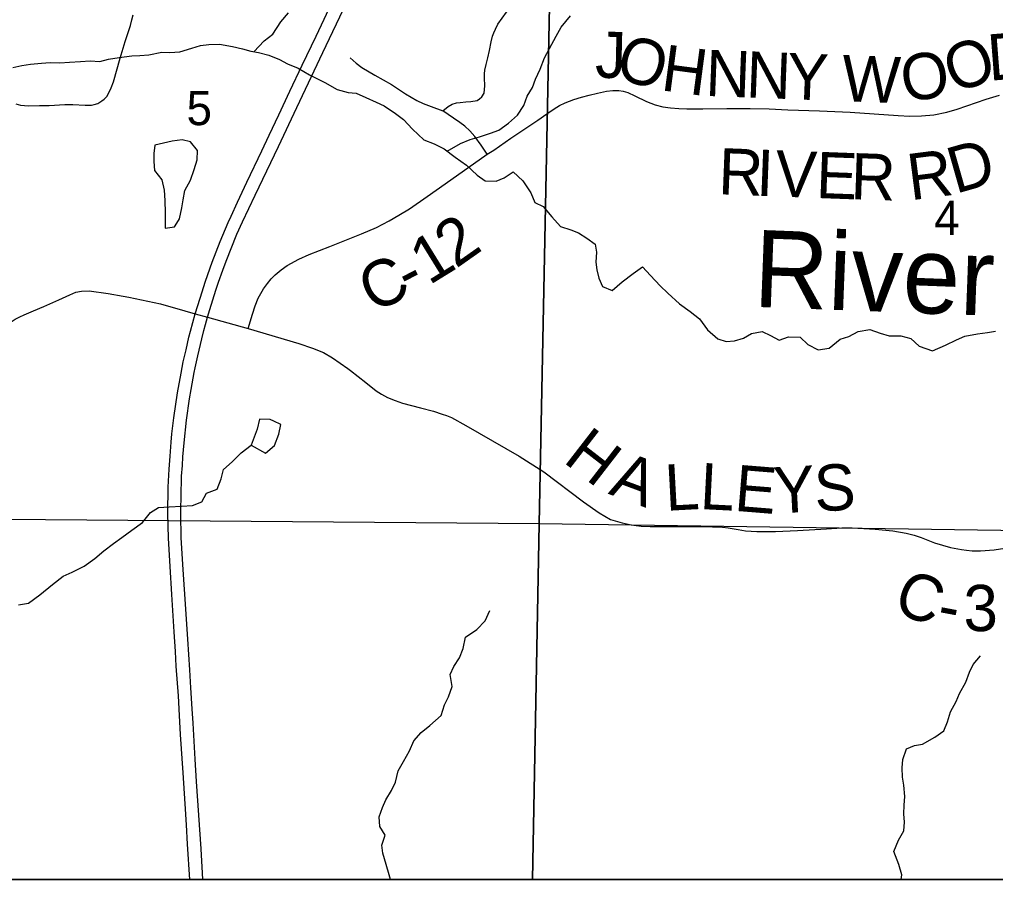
# Model space of a CAD drawing. Extents: x 0 to 34, y 0 to 22.
# Drawn here: x 6.166 to 7.364, y 14.573 to 15.63 of the extents above; entities that cross this region are included whole.
import ezdxf

# ---------------------------------------------------------------- set-up
doc = ezdxf.new("R2010")
doc.units = 0
for name, color, linetype in [('GM_X_Corporation', 7, 'Continuous'), ('GM_X_County_Road', 7, 'Continuous'), ('GM_X_County_Road_Text', 7, 'Continuous'), ('GM_X_Interstate_Route', 7, 'Continuous'), ('GM_X_Minor_Lake', 7, 'Continuous'), ('GM_X_Minor_River', 7, 'Continuous'), ('GM_X_Minor_River_Text', 7, 'Continuous'), ('GM_X_Section_Text', 7, 'Continuous'), ('GM_X_Township_Road', 7, 'Continuous'), ('SH_Text', 7, 'Continuous')]:
    doc.layers.add(name, color=color, linetype=linetype)

msp = doc.modelspace()

# ---------------------------------------------------------------- linework, layer by layer
at = {"layer": 'GM_X_Corporation'}
for points in [[(1.6311, 14.5734), (8.4311, 14.5734), (8.4311, 20.028)], [(3.7221, 14.5734), (8.4311, 14.5734), (8.4311, 16.0029), (7.8077, 16.0135), (7.8043, 16.0135), (6.9736, 16.0344), (6.9699, 16.0345), (6.7034, 16.04), (6.6909, 16.0403), (6.6873, 16.0404), (6.4721, 16.0449), (6.4668, 16.045), (5.0373, 16.0816)]]:
    msp.add_lwpolyline(points, dxfattribs=at)
for points in [[(5.82, 16.0635), (6.7585, 16.0372), (6.8244, 16.0368), (6.804, 15.0104), (5.7937, 15.0184)], [(6.8244, 16.0368), (7.8046, 16.0144), (7.7958, 14.9961), (6.804, 15.0104)], [(5.7869, 14.5734), (6.7958, 14.5734), (6.804, 15.0104), (5.7937, 15.0184)], [(6.7958, 14.5734), (7.7879, 14.5734), (7.7958, 14.9961), (6.804, 15.0104)]]:
    msp.add_lwpolyline(points, close=True, dxfattribs=at)
at = {"layer": 'GM_X_County_Road'}
for points in [[(6.296, 15.6029), (6.3022, 15.6226), (6.3042, 15.6295), (6.3057, 15.6357)], [(6.1617, 15.5261), (6.1673, 15.5246), (6.1721, 15.5241), (6.1773, 15.5239), (6.1905, 15.5241), (6.2027, 15.5241), (6.2217, 15.5253), (6.2317, 15.5253), (6.2469, 15.5246), (6.2543, 15.5247), (6.2577, 15.5252), (6.2621, 15.5267), (6.2673, 15.5297), (6.2701, 15.5319), (6.2732, 15.5353), (6.2763, 15.5404), (6.2787, 15.5459), (6.2814, 15.5532), (6.2898, 15.5824), (6.2933, 15.5944), (6.296, 15.6029)], [(6.8654, 15.5369), (6.8758, 15.5393), (6.8866, 15.5416), (6.8946, 15.5427), (6.902, 15.5427), (6.9071, 15.5419), (6.913, 15.5402), (6.9215, 15.5362), (6.9357, 15.5289), (6.9464, 15.5249), (6.9559, 15.5225), (6.9653, 15.5212), (6.9754, 15.5204), (6.9853, 15.5201), (7.005, 15.5201), (7.0346, 15.5206), (7.063, 15.5204), (7.0864, 15.52), (7.1096, 15.519), (7.1483, 15.5174), (7.1858, 15.5158), (7.2451, 15.5118), (7.2591, 15.5111), (7.2737, 15.5114), (7.2885, 15.5127), (7.3046, 15.516), (7.3175, 15.5196), (7.3531, 15.5319), (7.3695, 15.537)], [(6.447, 15.2501), (6.452, 15.268), (6.4554, 15.2779), (6.4591, 15.2873), (6.4624, 15.2933), (6.4658, 15.2991), (6.4706, 15.3057), (6.4752, 15.3112), (6.4801, 15.3162), (6.4874, 15.3224), (6.4947, 15.3276), (6.5089, 15.3355), (6.5216, 15.3411), (6.547, 15.3508), (6.5859, 15.3664), (6.6045, 15.3744), (6.6201, 15.3823), (6.6317, 15.3893), (6.6448, 15.3973), (6.6668, 15.4123), (6.6887, 15.4281), (6.7403, 15.4644), (6.7484, 15.4694), (6.7694, 15.4839), (6.7864, 15.4954), (6.8026, 15.5062), (6.8135, 15.5139), (6.8225, 15.52), (6.8291, 15.524), (6.8359, 15.5276), (6.8468, 15.5315), (6.8562, 15.5345), (6.8654, 15.5369)], [(6.1393, 15.2431), (6.1497, 15.2539), (6.1545, 15.2577), (6.1609, 15.2617), (6.1664, 15.2647), (6.1719, 15.2672), (6.1834, 15.2718), (6.1961, 15.2771), (6.2143, 15.2856), (6.2277, 15.2917), (6.2354, 15.2947), (6.2423, 15.2962), (6.2517, 15.2966), (6.2751, 15.2933), (6.2935, 15.29)], [(6.2935, 15.29), (6.3003, 15.2887), (6.3393, 15.2806), (6.3692, 15.2718), (6.3818, 15.2683), (6.3967, 15.2641), (6.447, 15.2501), (6.5089, 15.2317), (6.5259, 15.2261), (6.5394, 15.2206), (6.5502, 15.214), (6.5692, 15.2011), (6.5723, 15.1987)], [(6.5723, 15.1987), (6.5915, 15.1837), (6.6039, 15.1737), (6.6105, 15.1695), (6.6178, 15.1654), (6.6272, 15.1617), (6.6364, 15.1586), (6.6584, 15.1529), (6.6744, 15.1485), (6.6851, 15.1451), (6.6904, 15.1432), (6.6964, 15.1407), (6.7141, 15.1311), (6.7796, 15.0936), (6.8098, 15.0742), (6.8585, 15.0374), (6.8778, 15.0238), (6.8917, 15.0158), (6.906, 15.0114), (6.9172, 15.0091), (6.9294, 15.0076), (6.9403, 15.0071), (6.975, 15.007), (7.0044, 15.0071), (7.0292, 15.0061), (7.0361, 15.0054), (7.0485, 15.0034), (7.0573, 15.0016), (7.0712, 15.0007), (7.0943, 15.0007), (7.1215, 15.002), (7.1568, 15.0043), (7.1759, 15.0054), (7.1884, 15.0054), (7.2165, 15.0037), (7.2384, 15.0016), (7.2547, 14.9988), (7.2646, 14.9962), (7.2731, 14.9933), (7.2897, 14.987), (7.309, 14.9814), (7.3225, 14.9787), (7.3288, 14.9778), (7.3357, 14.9771), (7.346, 14.977), (7.3629, 14.9783), (7.3759, 14.9803)]]:
    msp.add_lwpolyline(points, dxfattribs=at)
at = {"layer": 'GM_X_Interstate_Route'}
for points in [[(6.3753, 14.5734), (6.3724, 14.6166), (6.3712, 14.6407), (6.3693, 14.6664), (6.3669, 14.7044), (6.3639, 14.7514), (6.3625, 14.7747), (6.3611, 14.799), (6.3586, 14.8353), (6.3577, 14.8536), (6.3561, 14.8778), (6.3548, 14.8973), (6.3533, 14.9235), (6.3509, 14.958), (6.349, 14.9927), (6.3484, 15.023), (6.3487, 15.0554), (6.3498, 15.0774), (6.3509, 15.0935), (6.3524, 15.1104), (6.3533, 15.1207), (6.3556, 15.1406), (6.36, 15.1711), (6.3645, 15.1955), (6.3671, 15.2092), (6.3706, 15.224), (6.3741, 15.2394), (6.376, 15.247), (6.3818, 15.2683), (6.3877, 15.2873), (6.3945, 15.3084), (6.4025, 15.3317), (6.4124, 15.357), (6.4224, 15.3806), (6.426, 15.3881), (6.4336, 15.4054), (6.4453, 15.4298), (6.4637, 15.4685), (6.4726, 15.4878), (6.4845, 15.5128), (6.4981, 15.5419), (6.5133, 15.5736), (6.5303, 15.6094), (6.5528, 15.6576)], [(6.3913, 14.5734), (6.3908, 14.5812), (6.389, 14.6111), (6.3835, 14.6939), (6.3817, 14.721), (6.3791, 14.7653), (6.378, 14.783), (6.3764, 14.8088), (6.3751, 14.8311), (6.3728, 14.8684), (6.3706, 14.8993), (6.3668, 14.9602), (6.3646, 14.9936), (6.3643, 15.0221), (6.3643, 15.0286), (6.3644, 15.0434), (6.365, 15.069), (6.3661, 15.0818), (6.3667, 15.0925), (6.3681, 15.1097), (6.371, 15.1377), (6.3747, 15.1638), (6.3768, 15.1754), (6.3806, 15.1963), (6.3817, 15.2017), (6.3849, 15.2165), (6.3899, 15.2377), (6.3925, 15.2476), (6.3943, 15.255), (6.3967, 15.2641), (6.3999, 15.2736), (6.4073, 15.2972), (6.4105, 15.3071), (6.4156, 15.3218), (6.4198, 15.333), (6.4329, 15.3659), (6.4399, 15.3811), (6.4553, 15.414), (6.4841, 15.4739), (6.5067, 15.5215), (6.5385, 15.5891), (6.5676, 15.6502)]]:
    msp.add_lwpolyline(points, dxfattribs=at)
at = {"layer": 'GM_X_Minor_Lake'}
for points in [[(6.3612, 15.383), (6.3625, 15.3851), (6.3655, 15.3984), (6.367, 15.4083), (6.3692, 15.4196), (6.376, 15.4326), (6.3805, 15.4455), (6.3842, 15.4576), (6.3846, 15.469), (6.3759, 15.4796), (6.3656, 15.4818), (6.3535, 15.4803), (6.3323, 15.4756)], [(6.3323, 15.4756), (6.3312, 15.465), (6.3312, 15.4555), (6.332, 15.4445), (6.3408, 15.4328), (6.3438, 15.4203), (6.3446, 15.4074), (6.3451, 15.3923), (6.3451, 15.3733), (6.3565, 15.3752), (6.3612, 15.383)], [(6.4785, 15.1364), (6.4738, 15.1386), (6.4609, 15.139), (6.458, 15.1265), (6.4504, 15.1071)], [(6.4504, 15.1071), (6.4683, 15.0969), (6.4792, 15.1064), (6.4845, 15.1205), (6.4871, 15.1322), (6.4785, 15.1364)]]:
    msp.add_lwpolyline(points, dxfattribs=at)
at = {"layer": 'GM_X_Minor_River'}
for points in [[(6.4538, 15.5902), (6.4663, 15.6035), (6.4773, 15.6119), (6.4871, 15.6271), (6.4965, 15.6381)], [(6.6912, 15.468), (6.7075, 15.4773), (6.7193, 15.4823), (6.731, 15.4858), (6.7442, 15.49), (6.7544, 15.4938), (6.7665, 15.5026), (6.7775, 15.5121), (6.7854, 15.5242), (6.7895, 15.5356), (6.7959, 15.5463), (6.7997, 15.5565), (6.8053, 15.5687), (6.8106, 15.5827), (6.817, 15.5941), (6.8249, 15.6093), (6.8313, 15.6203), (6.8426, 15.6344)], [(6.2037, 15.5768), (6.2154, 15.5764), (6.2275, 15.5772), (6.2411, 15.5784), (6.2529, 15.5789), (6.2646, 15.5781), (6.2752, 15.5812), (6.2885, 15.5832), (6.304, 15.5851), (6.3138, 15.5855), (6.3248, 15.5863), (6.3407, 15.5898), (6.3505, 15.5891), (6.363, 15.5902), (6.3778, 15.5945), (6.3884, 15.5979), (6.3986, 15.5991), (6.4118, 15.5995), (6.4277, 15.5965), (6.4399, 15.5939), (6.4501, 15.5909), (6.4596, 15.5891), (6.4721, 15.5861), (6.4853, 15.5808), (6.4952, 15.5755), (6.5081, 15.5699), (6.5221, 15.562), (6.5411, 15.5522), (6.5563, 15.5439), (6.5695, 15.5402), (6.5794, 15.5391), (6.5915, 15.5338), (6.604, 15.5282), (6.6139, 15.5236), (6.6279, 15.5142), (6.6374, 15.507), (6.6484, 15.4949), (6.6625, 15.4821), (6.6754, 15.4772), (6.6875, 15.4708), (6.7008, 15.4606), (6.7148, 15.4508), (6.7281, 15.4384), (6.738, 15.4316), (6.7512, 15.4312), (6.761, 15.4351), (6.7724, 15.4427), (6.7842, 15.4317), (6.7937, 15.417), (6.799, 15.4049), (6.8089, 15.4), (6.8195, 15.3875), (6.8305, 15.3754), (6.843, 15.3713), (6.8525, 15.3679), (6.8627, 15.3611), (6.873, 15.3539), (6.8745, 15.3441), (6.8738, 15.3316), (6.875, 15.3221), (6.8773, 15.3119), (6.8819, 15.302), (6.8936, 15.2971), (6.9061, 15.3074), (6.9197, 15.3177), (6.931, 15.3261), (6.9409, 15.3155), (6.9527, 15.3026), (6.9622, 15.2936), (6.9766, 15.2804), (6.9895, 15.2713), (7.0009, 15.2619), (7.0108, 15.2486), (7.0233, 15.2377), (7.0339, 15.2343), (7.0441, 15.2351), (7.0551, 15.2382), (7.0649, 15.2439), (7.0778, 15.2466), (7.088, 15.2417), (7.0986, 15.2357), (7.1104, 15.2399), (7.1244, 15.2395), (7.1339, 15.2305), (7.1468, 15.2241), (7.16, 15.226), (7.1736, 15.2371), (7.1842, 15.2405), (7.1959, 15.2466), (7.2103, 15.2489), (7.2228, 15.2444), (7.2338, 15.2414), (7.2482, 15.2411), (7.2603, 15.2381), (7.2706, 15.2287), (7.2869, 15.2227), (7.3031, 15.2296), (7.3167, 15.2364), (7.3266, 15.241), (7.3421, 15.2437), (7.3546, 15.2453)], [(6.1579, 15.5709), (6.1688, 15.5732), (6.1794, 15.5748), (6.1931, 15.576), (6.2037, 15.5768)], [(7.3546, 15.2453), (7.3644, 15.2468)], [(6.1648, 14.9108), (6.1773, 14.9127), (6.1909, 14.923), (6.2064, 14.9356), (6.2196, 14.9459), (6.2306, 14.9508), (6.2453, 14.9581), (6.2585, 14.9676), (6.2695, 14.9771), (6.2816, 14.9863), (6.2918, 14.9935), (6.3042, 15.0023), (6.3171, 15.0118), (6.3269, 15.0244), (6.3367, 15.0305), (6.35, 15.0313), (6.3651, 15.0321), (6.3783, 15.0329), (6.3901, 15.0371), (6.3957, 15.0481), (6.4086, 15.0527), (6.4135, 15.0656), (6.4165, 15.077), (6.427, 15.0865), (6.4384, 15.0976), (6.4504, 15.1071)], [(6.6216, 14.5734), (6.6198, 14.579), (6.6164, 14.5919), (6.6121, 14.6059), (6.611, 14.6154), (6.6151, 14.6279), (6.6086, 14.6385), (6.6075, 14.6503), (6.6116, 14.6617), (6.6157, 14.6712), (6.6229, 14.6826), (6.6278, 14.6928), (6.6311, 14.7069), (6.6375, 14.7183), (6.6451, 14.7316), (6.6503, 14.7437), (6.6594, 14.754), (6.67, 14.7624), (6.6836, 14.7749), (6.6877, 14.7878), (6.6926, 14.7977), (6.6975, 14.8103), (6.6948, 14.8254), (6.6993, 14.8349), (6.7064, 14.8456), (6.7109, 14.857), (6.7136, 14.871), (6.7275, 14.8805), (6.7377, 14.8912), (6.7434, 14.9037)], [(7.2485, 14.5734), (7.2495, 14.5793), (7.2456, 14.5918), (7.2395, 14.6077), (7.2455, 14.6218), (7.2519, 14.6332), (7.2527, 14.6438), (7.2519, 14.6541), (7.2522, 14.6647), (7.253, 14.6753), (7.2518, 14.6893), (7.2502, 14.6992), (7.2498, 14.7106), (7.2505, 14.7208), (7.255, 14.7337), (7.2649, 14.7379), (7.2747, 14.7395), (7.2898, 14.7482), (7.3008, 14.7562), (7.3053, 14.7669), (7.309, 14.7794), (7.3162, 14.792), (7.3203, 14.8018), (7.3279, 14.8159), (7.3324, 14.828), (7.3369, 14.8375), (7.3459, 14.8482)]]:
    msp.add_lwpolyline(points, dxfattribs=at)
at = {"layer": 'GM_X_Township_Road'}
for points in [[(6.6857, 15.5174), (6.6924, 15.5231), (6.6975, 15.5258), (6.7025, 15.5274), (6.7072, 15.528), (6.714, 15.5287), (6.7201, 15.5291), (6.7278, 15.5303), (6.731, 15.5323), (6.7339, 15.5348), (6.7365, 15.5393), (6.7373, 15.5483), (6.7368, 15.558), (6.7369, 15.5629), (6.7373, 15.5674), (6.7389, 15.5744), (6.741, 15.5827), (6.743, 15.5916), (6.7452, 15.6025), (6.747, 15.6092), (6.7484, 15.6135), (6.7504, 15.6179), (6.7534, 15.6242), (6.7745, 15.6537)], [(6.5719, 15.5826), (6.5794, 15.5762), (6.5865, 15.5709), (6.6023, 15.5613), (6.6227, 15.5499), (6.6401, 15.5384), (6.6471, 15.5342), (6.6541, 15.5304), (6.6618, 15.5268), (6.6714, 15.5228), (6.6857, 15.5174)], [(6.7403, 15.4644), (6.7331, 15.4755), (6.7253, 15.4861), (6.7191, 15.4932), (6.7129, 15.4987), (6.7067, 15.5034), (6.6991, 15.5084), (6.6857, 15.5174)]]:
    msp.add_lwpolyline(points, dxfattribs=at)
at = {"layer": 'SH_Text'}
msp.add_line((8.4311, 14.5734), (1.6311, 14.5734), dxfattribs=at)

# ---------------------------------------------------------------- texts
at = {"layer": 'GM_X_County_Road_Text'}
for s, rotation, p in [('J', 358.6884, (6.8725, 15.5584)), ('D', 4.456, (7.3567, 15.5545)), ('O', 344.3273, (6.8955, 15.5583)), ('O', 19.864, (7.3136, 15.5384)), ('H', 352.4603, (6.9523, 15.543)), ('N', 357.7876, (7.0076, 15.536)), ('N', 357.7847, (7.0575, 15.5341)), ('O', 8.7646, (7.2526, 15.5278)), ('Y', 357.7838, (7.1075, 15.5321)), ('W', 357.9212, (7.1751, 15.5295)), ('R', 357.8138, (7.0234, 15.4152)), ('I', 357.8225, (7.07, 15.4134)), ('D', 15.92, (7.3152, 15.4154)), ('V', 357.8174, (7.0933, 15.4125)), ('E', 357.8749, (7.1433, 15.4106)), ('R', 358.071, (7.186, 15.4091)), ('R', 7.301, (7.26, 15.4076)), ('2', 35.1671, (6.7019, 15.3233)), ('1', 31.6726, (6.6689, 15.3028)), ('C', 25.2838, (6.6, 15.2688)), ('-', 27.6156, (6.6444, 15.2898)), ('H', 322.2835, (6.8321, 15.0871)), ('A', 339.664, (6.888, 15.0474)), ('L', 3.0799, (6.9598, 15.0262)), ('L', 357.1404, (7.0007, 15.0285)), ('E', 355.3794, (7.0427, 15.0264)), ('Y', 2.8998, (7.0932, 15.0229)), ('S', 2.776, (7.1431, 15.0254)), ('C', 339.375, (7.2365, 14.9031)), ('3', 0.2788, (7.3252, 14.8784)), ('-', 349.3665, (7.2906, 14.8837))]:
    msp.add_text(s, height=0.0568, rotation=rotation, dxfattribs=at).set_placement(p)
at = {"layer": 'GM_X_Minor_River_Text'}
msp.add_text('River', height=0.09469, rotation=357.8426, dxfattribs=at).set_placement((7.0663, 15.2769))
at = {"layer": 'GM_X_Section_Text'}
for s, p in [('5', (6.3712, 15.5)), ('4', (7.2891, 15.3652))]:
    msp.add_text(s, height=0.0419, rotation=0, dxfattribs=at).set_placement(p)

doc.saveas('drawing.dxf')
